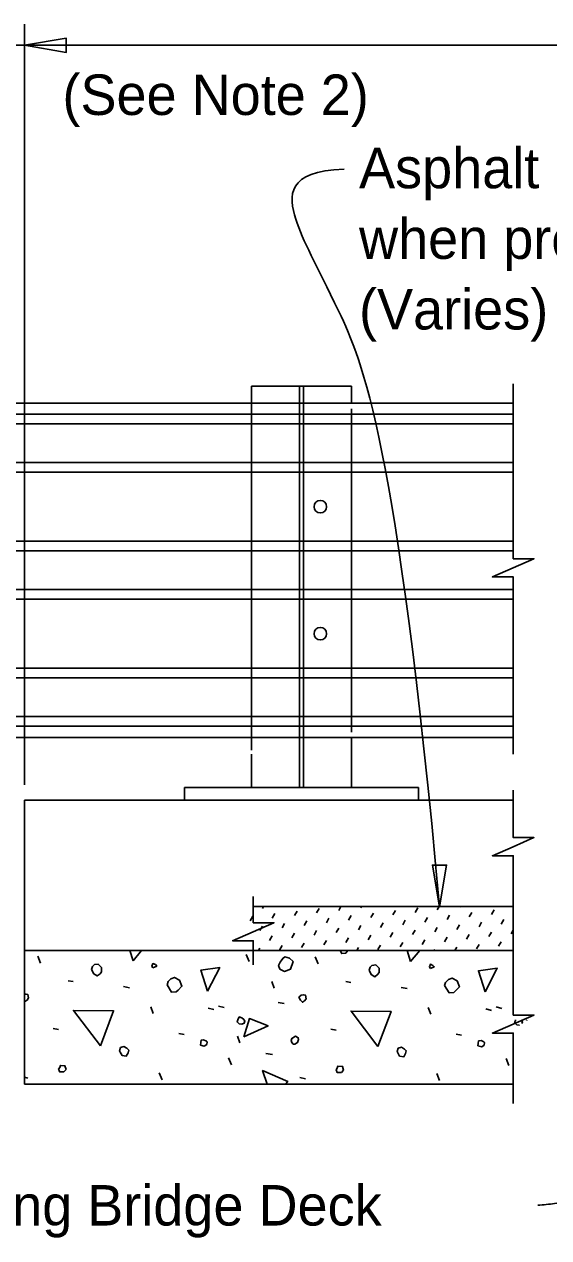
# Model space of a CAD drawing. Extents: x 21516.9 to 21589, y 56155.1 to 56195.
# Drawn here: x 21529.38 to 21532, y 56169.47 to 56175.52 of the extents above; entities that cross this region are included whole.
import ezdxf

# ---------------------------------------------------------------- set-up
doc = ezdxf.new("R2010")
doc.units = 0
for name, color, linetype in [('AdhocPoint_dp', 7, 'Continuous'), ('Border', 7, 'Continuous'), ('Patterning', 7, 'Continuous'), ('PlotBorder_dp', 7, 'Continuous'), ('SheetBorder_dp', 7, 'Continuous'), ('TextMisc', 7, 'Continuous')]:
    doc.layers.add(name, color=color, linetype=linetype)

msp = doc.modelspace()

# ---------------------------------------------------------------- linework, layer by layer
at = {"layer": 'AdhocPoint_dp'}
for p, q in [((21529.3813, 56170.2374), (21529.3813, 56171.6541)), ((21529.3813, 56171.6541), (21531.8195, 56171.6541)), ((21530.5229, 56171.123), (21531.8195, 56171.123)), ((21531.8195, 56170.9041), (21529.3813, 56170.9041)), ((21529.3813, 56170.2374), (21531.8195, 56170.2374))]:
    msp.add_line(p, q, dxfattribs=at)
at = {"layer": 'Border'}
for p, q in [((21530.5137, 56173.7167), (21530.5137, 56171.9037)), ((21530.7533, 56171.7167), (21530.7533, 56173.7167)), ((21530.7741, 56171.7167), (21530.7741, 56173.7167)), ((21531.0137, 56173.6048), (21531.0137, 56171.9929))]:
    msp.add_line(p, q, dxfattribs=at)
at = {"layer": 'Patterning'}
for p, q in [((21531.0137, 56173.7167), (21530.5137, 56173.7167)), ((21531.0137, 56173.7167), (21531.0137, 56173.6334)), ((21531.8195, 56173.6333), (21523.6791, 56173.6333)), ((21531.8195, 56171.9666), (21523.6791, 56171.9666)), ((21531.0137, 56171.9667), (21531.0137, 56171.7167)), ((21530.5137, 56171.8834), (21530.5137, 56171.7167)), ((21531.347, 56171.7167), (21530.1804, 56171.7167)), ((21530.1804, 56171.7167), (21530.1804, 56171.6542)), ((21531.0137, 56171.7167), (21530.5137, 56171.7167)), ((21531.347, 56171.6542), (21531.347, 56171.7167)), ((21531.347, 56171.6542), (21530.1804, 56171.6542))]:
    msp.add_line(p, q, dxfattribs=at)
for centre in [(21530.8574, 56173.1166), (21530.8574, 56172.4835)]:
    msp.add_circle(centre, 0.0312, dxfattribs=at)
at = {"layer": 'PlotBorder_dp'}
for p, q in [((21529.3813, 56171.7304), (21529.3813, 56175.5216)), ((21533.2773, 56175.4166), (21527.7324, 56175.4166))]:
    msp.add_line(p, q, dxfattribs=at)
for points in [[(21529.3812, 56175.4166), (21529.5895, 56175.3813), (21529.5895, 56175.4519)], [(21531.4525, 56171.1219), (21531.487, 56171.3302), (21531.4165, 56171.33)]]:
    msp.add_lwpolyline(points, close=True, dxfattribs=at)
for points in [[(21531.8195, 56171.8836), (21531.8195, 56172.7668), (21531.7162, 56172.7668), (21531.8195, 56172.8118), (21531.9228, 56172.8568), (21531.8195, 56172.8568), (21531.8195, 56173.7298)], [(21531.8195, 56170.9068), (21531.8195, 56171.3768), (21531.7162, 56171.3768), (21531.8195, 56171.4218), (21531.9228, 56171.4668), (21531.8195, 56171.4668), (21531.8195, 56171.7042)], [(21530.5229, 56170.8321), (21530.5229, 56170.953), (21530.4196, 56170.953), (21530.5229, 56170.998), (21530.6262, 56171.043), (21530.5229, 56171.043), (21530.5229, 56171.1736)], [(21531.8195, 56170.1417), (21531.8195, 56170.4923), (21531.7162, 56170.4923), (21531.8195, 56170.5373), (21531.9228, 56170.5823), (21531.8195, 56170.5823), (21531.8195, 56170.9068)]]:
    msp.add_lwpolyline(points, dxfattribs=at)
for points, degree in [([(21530.976, 56174.7994), (21530.6869, 56174.7915), (21530.7098, 56174.5384), (21530.8946, 56174.2331), (21531.2386, 56173.4543), (21531.4525, 56171.1219)], 3), ([(21532.8674, 56170.4673), (21532.6689, 56169.6813), (21531.9422, 56169.6346)], 2)]:
    msp.add_open_spline(points, degree=degree, dxfattribs=at)
at = {"layer": 'TextMisc'}
for p, q in [((21523.6791, 56173.5778), (21531.8195, 56173.5778)), ((21523.6791, 56173.5295), (21531.8195, 56173.5295)), ((21523.6791, 56173.3367), (21531.8195, 56173.3367)), ((21523.6791, 56173.2885), (21531.8195, 56173.2885)), ((21523.6791, 56172.9445), (21531.8195, 56172.9445)), ((21523.6791, 56172.8963), (21531.8195, 56172.8963)), ((21523.6791, 56172.7035), (21531.8195, 56172.7035)), ((21523.6791, 56172.6554), (21531.8195, 56172.6554)), ((21523.6791, 56172.3114), (21531.8195, 56172.3114)), ((21523.6791, 56172.2632), (21531.8195, 56172.2632)), ((21523.6791, 56172.0704), (21531.8195, 56172.0704)), ((21523.6791, 56172.0221), (21531.8195, 56172.0221)), ((21530.5687, 56171.1144), (21530.5737, 56171.123)), ((21530.8388, 56171.0915), (21530.8518, 56171.1139)), ((21530.9494, 56171.1045), (21530.9602, 56171.123)), ((21531.0601, 56171.1174), (21531.0633, 56171.123)), ((21531.3302, 56171.0945), (21531.3431, 56171.1169)), ((21531.4408, 56171.1075), (21531.4498, 56171.123)), ((21531.5514, 56171.1204), (21531.5529, 56171.123)), ((21530.5069, 56171.0526), (21530.5199, 56171.075)), ((21530.6175, 56171.0656), (21530.6305, 56171.088)), ((21530.7282, 56171.0785), (21530.7411, 56171.1009)), ((21530.8876, 56171.0427), (21530.9006, 56171.065)), ((21530.9983, 56171.0556), (21531.0112, 56171.078)), ((21531.1089, 56171.0686), (21531.1219, 56171.091)), ((21531.2195, 56171.0815), (21531.2325, 56171.1039)), ((21531.2684, 56171.0327), (21531.2813, 56171.0551)), ((21531.379, 56171.0457), (21531.392, 56171.0681)), ((21531.4896, 56171.0586), (21531.5026, 56171.081)), ((21531.6003, 56171.0716), (21531.6132, 56171.094)), ((21531.7109, 56171.0846), (21531.7239, 56171.107)), ((21531.7597, 56171.0357), (21531.7727, 56171.0581)), ((21530.5557, 56171.0038), (21530.5687, 56171.0262)), ((21530.6664, 56171.0167), (21530.6793, 56171.0391)), ((21530.777, 56171.0297), (21530.79, 56171.0521)), ((21530.8258, 56170.9809), (21530.8388, 56171.0032)), ((21530.9365, 56170.9938), (21530.9494, 56171.0162)), ((21531.0471, 56171.0068), (21531.0601, 56171.0292)), ((21531.1577, 56171.0197), (21531.1707, 56171.0421)), ((21531.2066, 56170.9709), (21531.2195, 56170.9933)), ((21531.3172, 56170.9839), (21531.3302, 56171.0063)), ((21531.4278, 56170.9968), (21531.4408, 56171.0192)), ((21531.5385, 56171.0098), (21531.5514, 56171.0322)), ((21531.6491, 56171.0228), (21531.6621, 56171.0452)), ((21531.6979, 56170.9739), (21531.7109, 56170.9963)), ((21531.8086, 56170.9869), (21531.8195, 56171.0058)), ((21530.6046, 56170.9549), (21530.6175, 56170.9773)), ((21530.7152, 56170.9679), (21530.7282, 56170.9903)), ((21530.764, 56170.9191), (21530.777, 56170.9414)), ((21530.8747, 56170.932), (21530.8876, 56170.9544)), ((21530.9853, 56170.945), (21530.9983, 56170.9674)), ((21531.0959, 56170.9579), (21531.1089, 56170.9803)), ((21531.1448, 56170.9091), (21531.1577, 56170.9315)), ((21531.2554, 56170.9221), (21531.2684, 56170.9445)), ((21531.366, 56170.935), (21531.379, 56170.9574)), ((21531.4767, 56170.948), (21531.4896, 56170.9704)), ((21531.5873, 56170.961), (21531.6003, 56170.9834)), ((21531.6361, 56170.9121), (21531.6491, 56170.9345)), ((21531.7468, 56170.9251), (21531.7597, 56170.9475)), ((21529.4615, 56170.841), (21529.4474, 56170.8763)), ((21530.5021, 56170.8492), (21530.488, 56170.8845)), ((21530.5491, 56170.9041), (21530.5557, 56170.9155)), ((21530.6534, 56170.9061), (21530.6664, 56170.9285)), ((21530.8462, 56170.8374), (21530.8321, 56170.8728)), ((21530.9356, 56170.9041), (21530.9365, 56170.9056)), ((21531.0388, 56170.9041), (21531.0471, 56170.9185)), ((21531.4252, 56170.9041), (21531.4278, 56170.9086)), ((21531.5284, 56170.9041), (21531.5385, 56170.9216)), ((21529.5994, 56170.7526), (21529.6242, 56170.749)), ((21530.6276, 56170.7166), (21530.6152, 56170.7502)), ((21529.8752, 56170.7243), (21529.9052, 56170.719)), ((21530.9841, 56170.749), (21531.0088, 56170.7455)), ((21531.2599, 56170.7207), (21531.2899, 56170.7154)), ((21530.6464, 56170.6447), (21530.6765, 56170.6394)), ((21530.0237, 56170.5899), (21530.0113, 56170.6235)), ((21530.2977, 56170.6164), (21530.326, 56170.6094)), ((21530.3501, 56170.6264), (21530.3784, 56170.6194)), ((21531.4083, 56170.5864), (21531.396, 56170.62)), ((21531.6824, 56170.6129), (21531.7106, 56170.6058)), ((21531.7348, 56170.6229), (21531.763, 56170.6158)), ((21529.5252, 56170.5157), (21529.5517, 56170.5104)), ((21530.9098, 56170.5122), (21530.9364, 56170.5068)), ((21530.1509, 56170.4909), (21530.1775, 56170.4856)), ((21530.4561, 56170.4438), (21530.4438, 56170.4774)), ((21531.5356, 56170.4874), (21531.5621, 56170.4821)), ((21530.5863, 56170.3902), (21530.6182, 56170.3866)), ((21530.4137, 56170.3342), (21530.3996, 56170.3696)), ((21531.7984, 56170.3307), (21531.7843, 56170.3661)), ((21529.3813, 56170.2723), (21529.3979, 56170.2682)), ((21530.0679, 56170.2594), (21530.0537, 56170.2947)), ((21530.7543, 56170.2717), (21530.7826, 56170.2647)), ((21531.4525, 56170.2558), (21531.4384, 56170.2912))]:
    msp.add_line(p, q, dxfattribs=at)
for points in [[(21529.9229, 56170.8533), (21529.9064, 56170.9041)], [(21529.9659, 56170.9041), (21529.9229, 56170.8533)], [(21530.6559, 56170.812), (21530.6789, 56170.7997), (21530.7089, 56170.812), (21530.7213, 56170.8492), (21530.7036, 56170.8668), (21530.6807, 56170.8721), (21530.67, 56170.8651), (21530.6577, 56170.8456), (21530.6488, 56170.8297), (21530.6559, 56170.812)], [(21530.9561, 56170.9041), (21530.9646, 56170.8887), (21530.9841, 56170.8905), (21530.9929, 56170.9028), (21530.993, 56170.9041)], [(21531.3076, 56170.8498), (21531.2899, 56170.9041)], [(21531.3535, 56170.9041), (21531.3076, 56170.8498)], [(21529.7161, 56170.8091), (21529.7267, 56170.7879), (21529.7444, 56170.7773), (21529.7585, 56170.7879), (21529.7656, 56170.7985), (21529.7656, 56170.8197), (21529.7497, 56170.8357), (21529.7302, 56170.8339), (21529.7214, 56170.825), (21529.7161, 56170.8091)], [(21530.0219, 56170.818), (21530.0413, 56170.8268), (21530.0343, 56170.8339), (21530.0219, 56170.8392), (21530.0166, 56170.8268), (21530.0219, 56170.818)], [(21530.2953, 56170.7024), (21530.2617, 56170.8067), (21530.3554, 56170.8191), (21530.2953, 56170.7024)], [(21531.1008, 56170.8056), (21531.1114, 56170.7844), (21531.129, 56170.7738), (21531.1432, 56170.7844), (21531.1503, 56170.795), (21531.1503, 56170.8162), (21531.1343, 56170.8321), (21531.1149, 56170.8303), (21531.1061, 56170.8215), (21531.1008, 56170.8056)], [(21531.4066, 56170.8144), (21531.426, 56170.8233), (21531.419, 56170.8303), (21531.4066, 56170.8357), (21531.4013, 56170.8233), (21531.4066, 56170.8144)], [(21531.68, 56170.6989), (21531.6464, 56170.8032), (21531.7401, 56170.8156), (21531.68, 56170.6989)], [(21530.0926, 56170.7331), (21530.1156, 56170.696), (21530.1386, 56170.6978), (21530.1474, 56170.7066), (21530.1669, 56170.7261), (21530.1545, 56170.7561), (21530.1297, 56170.7702), (21530.1121, 56170.7632), (21530.0979, 56170.749), (21530.0926, 56170.7331)], [(21531.4773, 56170.7296), (21531.5003, 56170.6925), (21531.5233, 56170.6942), (21531.5321, 56170.7031), (21531.5515, 56170.7225), (21531.5392, 56170.7526), (21531.5144, 56170.7667), (21531.4967, 56170.7596), (21531.4826, 56170.7455), (21531.4773, 56170.7296)], [(21529.3813, 56170.6525), (21529.3837, 56170.65), (21529.3943, 56170.6571), (21529.4014, 56170.6677), (21529.3979, 56170.6854), (21529.389, 56170.6872), (21529.3813, 56170.6861)], [(21530.7578, 56170.6571), (21530.7684, 56170.6465), (21530.779, 56170.6536), (21530.7861, 56170.6642), (21530.7826, 56170.6819), (21530.7737, 56170.6836), (21530.7613, 56170.6819), (21530.7507, 56170.6712), (21530.7578, 56170.6571)], [(21529.7603, 56170.4291), (21529.6259, 56170.6058), (21529.8257, 56170.6041), (21529.7603, 56170.4291)], [(21530.4526, 56170.538), (21530.465, 56170.5363), (21530.4774, 56170.5416), (21530.4809, 56170.5522), (21530.4756, 56170.561), (21530.465, 56170.5681), (21530.4526, 56170.5734), (21530.4455, 56170.5593), (21530.442, 56170.5486), (21530.4526, 56170.538)], [(21531.1449, 56170.4255), (21531.0106, 56170.6023), (21531.2104, 56170.6005), (21531.1449, 56170.4255)], [(21530.475, 56170.4733), (21530.5032, 56170.5652), (21530.5969, 56170.5281), (21530.475, 56170.4733)], [(21531.8316, 56170.5585), (21531.8302, 56170.5557), (21531.8267, 56170.5451), (21531.8373, 56170.5345)], [(21531.8373, 56170.5345), (21531.8497, 56170.5327), (21531.8515, 56170.5335)], [(21531.8629, 56170.5405), (21531.8656, 56170.5486), (21531.8603, 56170.5575), (21531.8587, 56170.5585)], [(21531.8858, 56170.5547), (21531.887, 56170.5585)], [(21530.2588, 56170.4326), (21530.2782, 56170.4273), (21530.2906, 56170.4361), (21530.2924, 56170.4485), (21530.2888, 56170.452), (21530.2747, 56170.4591), (21530.2623, 56170.4573), (21530.2606, 56170.445), (21530.2588, 56170.4326)], [(21530.7225, 56170.4379), (21530.7295, 56170.4379), (21530.7437, 56170.445), (21530.749, 56170.4609), (21530.7472, 56170.4697), (21530.7331, 56170.4768), (21530.7154, 56170.4662), (21530.7118, 56170.4556), (21530.7154, 56170.445), (21530.7225, 56170.4379)], [(21531.6435, 56170.4291), (21531.6629, 56170.4238), (21531.6753, 56170.4326), (21531.677, 56170.445), (21531.6735, 56170.4485), (21531.6594, 56170.4556), (21531.647, 56170.4538), (21531.6452, 56170.4414), (21531.6435, 56170.4291)], [(21529.8593, 56170.3972), (21529.8681, 56170.3813), (21529.8893, 56170.3778), (21529.8982, 56170.3937), (21529.9017, 56170.4079), (21529.8929, 56170.4167), (21529.8769, 56170.4255), (21529.861, 56170.4202), (21529.8557, 56170.4043), (21529.8593, 56170.3972)], [(21531.2439, 56170.3937), (21531.2528, 56170.3778), (21531.274, 56170.3743), (21531.2828, 56170.3902), (21531.2864, 56170.4043), (21531.2775, 56170.4132), (21531.2616, 56170.422), (21531.2457, 56170.4167), (21531.2404, 56170.4008), (21531.2439, 56170.3937)], [(21529.557, 56170.3), (21529.5782, 56170.3), (21529.5888, 56170.3106), (21529.5835, 56170.3301), (21529.5605, 56170.3318), (21529.557, 56170.3212), (21529.5517, 56170.3124), (21529.557, 56170.3), (21529.5534, 56170.3036)], [(21530.9417, 56170.2965), (21530.9629, 56170.2965), (21530.9735, 56170.3071), (21530.9682, 56170.3265), (21530.9452, 56170.3283), (21530.9417, 56170.3177), (21530.9364, 56170.3089), (21530.9417, 56170.2965), (21530.9381, 56170.3)], [(21530.5916, 56170.2374), (21530.5693, 56170.3059), (21530.6948, 56170.2511), (21530.6832, 56170.2374)], [(21530.2896, 56170.2374), (21530.2829, 56170.2388), (21530.2789, 56170.2374)]]:
    msp.add_lwpolyline(points, dxfattribs=at)

# ---------------------------------------------------------------- texts
at = {"layer": 'PlotBorder_dp'}
for s, p in [('Asphalt Overlay', (21531.0506, 56174.7041)), ('when present', (21531.0506, 56174.3521)), ('(Varies)', (21531.0506, 56174.0001))]:
    msp.add_text(s, height=0.2016, dxfattribs=at).set_placement(p)
at = {"layer": 'SheetBorder_dp'}
for s, p in [('(See Note 2)', (21529.5709, 56175.0695)), ('Existing Bridge Deck', (21528.676, 56169.5333))]:
    msp.add_text(s, height=0.2016, dxfattribs=at).set_placement(p)

doc.saveas('drawing.dxf')
